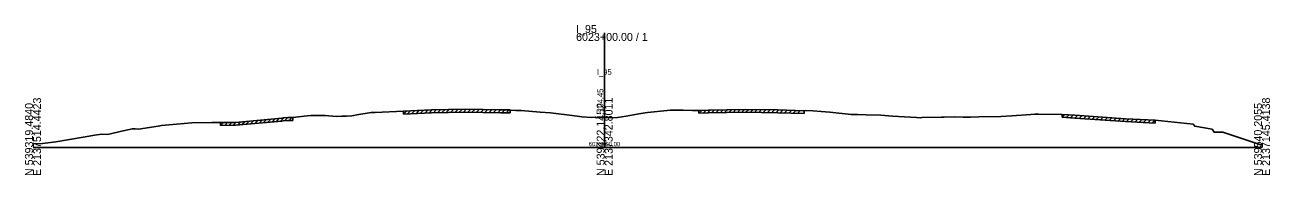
# Model space of a CAD drawing. Extents: x -12534 to 3403, y -1332 to 21983.
# Drawn here: x 997.2 to 1432.8, y 12990.3 to 13043 of the extents above; entities that cross this region are included whole.
import ezdxf

# ---------------------------------------------------------------- set-up
doc = ezdxf.new("R2010")
doc.units = 0
for name, color, linetype in [('RD_GPK_XS_Cell', 7, 'Continuous'), ('RD_XS_ExGround', 7, 'Continuous'), ('RD_XS_ExPaveRet', 7, 'Continuous'), ('RD_XS_TX_Baseline', 7, 'Continuous'), ('RD_XS_TX_Elev_EX', 7, 'Continuous'), ('RD_XS_TX_Station', 7, 'Continuous')]:
    doc.layers.add(name, color=color, linetype=linetype)

msp = doc.modelspace()

# ---------------------------------------------------------------- linework, layer by layer
at = {"layer": 'RD_GPK_XS_Cell'}
for p, q in [((1200, 13000), (1200, 13040.13)), ((1000, 13000), (1200, 13000)), ((1200, 13000), (1430, 13000))]:
    msp.add_line(p, q, dxfattribs=at)
at = {"layer": 'RD_XS_ExGround'}
msp.add_lwpolyline([(1000, 13001.26), (1003.26, 13001.45), (1008, 13001.98), (1022.38, 13004.44), (1023.22, 13004.58), (1023.82, 13004.66), (1026.03, 13004.57), (1031.55, 13005.87), (1034.77, 13006.54), (1035.73, 13006.54), (1036.96, 13006.41), (1043.77, 13007.47), (1044.96, 13007.66), (1047.48, 13007.91), (1055.61, 13008.66), (1062.61, 13008.72), (1065.57, 13008.73), (1070.8, 13008.81), (1087.08, 13010.22), (1087.47, 13010.36), (1089.1, 13010.51), (1090.85, 13010.51), (1095.94, 13011.04), (1097.26, 13011.15), (1099.22, 13011.16), (1102.16, 13011.16), (1106.18, 13010.82), (1108.03, 13010.94), (1109.68, 13010.97), (1111.58, 13011.13), (1112.23, 13011.26), (1113.3, 13011.43), (1118.35, 13012.2), (1119.3, 13012.28), (1119.69, 13012.29), (1129.58, 13012.72), (1139.4, 13013.15), (1151.36, 13013.38), (1163.69, 13013.16), (1166.67, 13013.17), (1166.99, 13013.11), (1168.93, 13013.01), (1170.82, 13012.96), (1177.48, 13012.39), (1181.06, 13012.13), (1188.67, 13011.18), (1191.24, 13010.85), (1192.05, 13010.75), (1195.44, 13010.5), (1196.7, 13010.58), (1197, 13010.4), (1200, 13010.45), (1201.88, 13010.49), (1202.28, 13010.44), (1204.45, 13010.48), (1207.56, 13011.03), (1212.67, 13011.94), (1214.95, 13012.22), (1221.93, 13012.94), (1222.91, 13013.05), (1223.21, 13013.06), (1227.43, 13013.09), (1230.7, 13012.99), (1232.94, 13012.97), (1236.29, 13013.12), (1249.13, 13013.33), (1260.59, 13013.16), (1269.84, 13012.87), (1270.32, 13012.94), (1272.83, 13012.79), (1275.72, 13012.59), (1278.8, 13012.33), (1286.25, 13011.61), (1288.45, 13011.5), (1291.48, 13011.44), (1296.65, 13011.28), (1300.74, 13011.03), (1309.14, 13010.46), (1310.47, 13010.4), (1310.93, 13010.47), (1317.84, 13010.67), (1318.78, 13010.66), (1322.5, 13010.7), (1325.5, 13010.64), (1326.57, 13010.58), (1328, 13010.61), (1330.98, 13010.72), (1338.62, 13010.88), (1342.47, 13011.1), (1349.07, 13011.59), (1350.55, 13011.69), (1351.8, 13011.68), (1360.04, 13011.61), (1364.57, 13011.29), (1382.25, 13010.08), (1392.66, 13009.53), (1405.95, 13008.12), (1406.48, 13007.41), (1412.57, 13006.41), (1413.24, 13005.39), (1416.3, 13005.42), (1430, 13000.78)], dxfattribs=at)
at = {"layer": 'RD_XS_ExPaveRet'}
for p, q in [((1077.57, 13008.4), (1078.67, 13009.49)), ((1079.07, 13008.53), (1080.17, 13009.62)), ((1080.57, 13008.66), (1081.67, 13009.75)), ((1082.07, 13008.79), (1083.17, 13009.88)), ((1083.57, 13008.92), (1084.67, 13010.01)), ((1085.07, 13009.05), (1086.17, 13010.14)), ((1086.57, 13009.18), (1087.79, 13010.39)), ((1087.47, 13009.36), (1089.1, 13009.51)), ((1088.07, 13009.41), (1089.16, 13010.51)), ((1089.1, 13009.51), (1090.85, 13009.51)), ((1089.57, 13009.51), (1090.57, 13010.51)), ((1090.85, 13010.51), (1090.85, 13009.51)), ((1129.58, 13011.72), (1130.62, 13012.76)), ((1129.58, 13011.72), (1129.58, 13012.72)), ((1129.58, 13011.72), (1139.4, 13012.15)), ((1131.08, 13011.78), (1132.12, 13012.83)), ((1132.58, 13011.85), (1133.62, 13012.9)), ((1134.08, 13011.92), (1135.12, 13012.96)), ((1135.58, 13011.98), (1136.62, 13013.03)), ((1137.08, 13012.05), (1138.12, 13013.09)), ((1138.58, 13012.11), (1139.62, 13013.16)), ((1139.4, 13012.15), (1151.36, 13012.38)), ((1140.08, 13012.16), (1141.1, 13013.18)), ((1141.58, 13012.19), (1142.6, 13013.21)), ((1143.08, 13012.22), (1144.1, 13013.24)), ((1144.58, 13012.25), (1145.6, 13013.27)), ((1146.08, 13012.28), (1147.1, 13013.3)), ((1147.58, 13012.3), (1148.6, 13013.32)), ((1149.08, 13012.33), (1150.1, 13013.35)), ((1150.58, 13012.36), (1151.59, 13013.37)), ((1151.36, 13012.38), (1163.69, 13012.16)), ((1152.08, 13012.36), (1153.06, 13013.35)), ((1153.58, 13012.34), (1154.56, 13013.32)), ((1155.08, 13012.31), (1156.06, 13013.29)), ((1156.58, 13012.28), (1157.56, 13013.27)), ((1158.08, 13012.26), (1159.06, 13013.24)), ((1159.58, 13012.23), (1160.56, 13013.21)), ((1161.08, 13012.2), (1162.06, 13013.19)), ((1162.58, 13012.18), (1163.56, 13013.16)), ((1163.69, 13012.16), (1166.67, 13012.17)), ((1164.08, 13012.16), (1165.08, 13013.16)), ((1165.58, 13012.16), (1166.58, 13013.17)), ((1166.67, 13012.17), (1166.99, 13012.11)), ((1166.99, 13013.11), (1166.99, 13012.11)), ((1232.94, 13011.97), (1233.98, 13013.01)), ((1232.94, 13011.97), (1232.94, 13012.97)), ((1232.94, 13011.97), (1236.29, 13012.12)), ((1234.44, 13012.03), (1235.48, 13013.08)), ((1235.94, 13012.1), (1236.96, 13013.13)), ((1236.29, 13012.12), (1249.13, 13012.33)), ((1237.44, 13012.14), (1238.45, 13013.15)), ((1238.94, 13012.16), (1239.95, 13013.18)), ((1240.44, 13012.19), (1241.45, 13013.2)), ((1241.94, 13012.21), (1242.95, 13013.23)), ((1243.44, 13012.24), (1244.45, 13013.26)), ((1244.94, 13012.26), (1245.95, 13013.28)), ((1246.44, 13012.29), (1247.45, 13013.31)), ((1247.94, 13012.31), (1248.95, 13013.33)), ((1249.13, 13012.33), (1260.59, 13012.16)), ((1249.44, 13012.33), (1250.42, 13013.31)), ((1250.94, 13012.31), (1251.92, 13013.29)), ((1252.44, 13012.28), (1253.42, 13013.27)), ((1253.94, 13012.26), (1254.92, 13013.25)), ((1255.44, 13012.24), (1256.42, 13013.22)), ((1256.94, 13012.21), (1257.92, 13013.2)), ((1258.44, 13012.19), (1259.42, 13013.18)), ((1259.94, 13012.17), (1260.92, 13013.15)), ((1260.59, 13012.16), (1269.84, 13011.87)), ((1261.44, 13012.13), (1262.4, 13013.1)), ((1262.94, 13012.09), (1263.9, 13013.06)), ((1264.44, 13012.04), (1265.4, 13013.01)), ((1265.94, 13011.99), (1266.9, 13012.96)), ((1267.44, 13011.94), (1268.4, 13012.91)), ((1269.84, 13012.87), (1269.84, 13011.87)), ((1360.04, 13010.61), (1360.04, 13011.61)), ((1360.04, 13010.61), (1360.98, 13011.55)), ((1360.04, 13010.61), (1364.57, 13010.29)), ((1361.54, 13010.51), (1362.48, 13011.44)), ((1363.04, 13010.4), (1363.98, 13011.34)), ((1364.54, 13010.3), (1365.48, 13011.23)), ((1364.57, 13010.29), (1382.25, 13009.08)), ((1366.04, 13010.19), (1366.98, 13011.13)), ((1367.54, 13010.09), (1368.48, 13011.03)), ((1369.04, 13009.99), (1369.98, 13010.92)), ((1370.54, 13009.88), (1371.48, 13010.82)), ((1372.04, 13009.78), (1372.98, 13010.72)), ((1373.54, 13009.68), (1374.48, 13010.61)), ((1375.04, 13009.58), (1375.98, 13010.51)), ((1376.54, 13009.47), (1377.48, 13010.41)), ((1378.04, 13009.37), (1378.98, 13010.31)), ((1379.54, 13009.27), (1380.48, 13010.2)), ((1381.04, 13009.16), (1381.98, 13010.1)), ((1382.54, 13009.07), (1383.49, 13010.02)), ((1384.04, 13008.99), (1384.99, 13009.94)), ((1385.54, 13008.91), (1386.49, 13009.86)), ((1387.04, 13008.83), (1387.99, 13009.78)), ((1388.54, 13008.75), (1389.49, 13009.7)), ((1390.04, 13008.67), (1390.99, 13009.62)), ((1391.54, 13008.59), (1392.49, 13009.54)), ((1392.66, 13009.53), (1392.66, 13008.53)), ((1065.57, 13007.73), (1066.59, 13008.74)), ((1065.57, 13007.73), (1065.57, 13008.73)), ((1065.57, 13007.73), (1070.8, 13007.81)), ((1067.07, 13007.75), (1068.09, 13008.77)), ((1068.57, 13007.77), (1069.59, 13008.79)), ((1070.07, 13007.8), (1071.11, 13008.83)), ((1070.8, 13007.81), (1087.08, 13009.22)), ((1071.57, 13007.87), (1072.67, 13008.97)), ((1073.07, 13008.01), (1074.17, 13009.1)), ((1074.57, 13008.14), (1075.67, 13009.23)), ((1076.07, 13008.27), (1077.17, 13009.36)), ((1087.08, 13009.22), (1087.47, 13009.36)), ((1382.25, 13009.08), (1392.66, 13008.53))]:
    msp.add_line(p, q, dxfattribs=at)

# ---------------------------------------------------------------- texts
at = {"layer": 'RD_GPK_XS_Cell'}
for s, p in [('6023+00.00 / 1', (1190, 13037.33)), ('I_95', (1190, 13040.13))]:
    msp.add_text(s, height=2.8, dxfattribs=at).set_placement(p)
for s, p in [('N 539319.4840', (1000, 12990)), ('E 2137514.4423', (1002.8, 12990)), ('N 539422.1452', (1200, 12990)), ('E 2137342.8011', (1202.8, 12990)), ('N 539540.2055', (1430, 12990)), ('E 2137145.4138', (1432.8, 12990))]:
    msp.add_text(s, height=2.8, rotation=90, dxfattribs=at).set_placement(p)
at = {"layer": 'RD_XS_TX_Baseline'}
msp.add_text('I_95', height=2, dxfattribs=at).set_placement((1197.28, 13025.45))
at = {"layer": 'RD_XS_TX_Elev_EX'}
msp.add_text('104.45', height=2, rotation=90, dxfattribs=at).set_placement((1199.5, 13012.45))
at = {"layer": 'RD_XS_TX_Station'}
msp.add_text('6023+00.00', height=1.5, dxfattribs=at).set_placement((1194.45, 13000.45))

doc.saveas('drawing.dxf')
